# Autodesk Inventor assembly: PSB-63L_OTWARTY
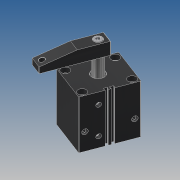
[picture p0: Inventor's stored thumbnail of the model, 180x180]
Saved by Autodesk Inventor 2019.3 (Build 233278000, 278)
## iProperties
Company: Î¢ÈíÖÐ¹ú
Created: 2013-04
Part Number: PSB-63L_OTWARTY
Material: Ogólny
Description: STEP AP203
Document SubType Name: Assembly
Designer: CADENGINEERING4
Sending System: SolidWorks 2010
Preprocessor: SwSTEP 2.0
Title: PSB-L6390-1515-00.STEP
Author: Î¢ÈíÓÃ»§
Revision Number: ÈÎºÎ
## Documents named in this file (11)
- E:\SERWER_ZAPAS\Pneumatic\PSB PNEUMATIC SWING\PSB-63\PSB-63L_OTWARTY.iam
- E:\SERWER_ZAPAS\Pneumatic\PSB PNEUMATIC SWING\PSB-63\PSB-L63-90-15-15-01.ipt
- E:\SERWER_ZAPAS\Pneumatic\PSB PNEUMATIC SWING\PSB-63\¸ÖÖé4.ipt
- E:\SERWER_ZAPAS\Pneumatic\PSB PNEUMATIC SWING\PSB-63\hex socket set screws with flat point gb_GB_FASTENER_SCREWS_HSFP M5X8-N.ipt
- E:\SERWER_ZAPAS\Pneumatic\PSB PNEUMATIC SWING\PSB-63\PSB-L63-90-15-15-04.ipt
- E:\SERWER_ZAPAS\Pneumatic\PSB PNEUMATIC SWING\PSB-63\PSB-L63-90-15-15-02.ipt
- E:\SERWER_ZAPAS\Pneumatic\PSB PNEUMATIC SWING\PSB-63\PSB-L63-90-15-15-05.ipt
- E:\SERWER_ZAPAS\Pneumatic\PSB PNEUMATIC SWING\PSB-63\hexagon socket head cap screws gb_GB_FASTENER_SCREWS_HSHCS M10X20-N.ipt
- E:\SERWER_ZAPAS\Pneumatic\PSB PNEUMATIC SWING\PSB-63\s¸Ë2.ipt
- E:\SERWER_ZAPAS\Pneumatic\PSB PNEUMATIC SWING\PSB-63\PSB-L63-90-15-15-03.ipt
- E:\SERWER_ZAPAS\Pneumatic\PSB PNEUMATIC SWING\PSB-63\4x40.ipt
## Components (14 placed, 14 different names)
1. PSB-L63-90-15-15-01_1 — Zestawiające:1, Zestawiające:2, Zestawiające:4, Kątowe:1
2. ¸ÖÖé4_2 — Zestawiające:10
3. hex socket set screws with flat point gb_GB_FASTENER_SCREWS_HSFP M5X8-N_3 — Zestawiające:10
4. hex socket set screws with flat point gb_GB_FASTENER_SCREWS_HSFP M5X8-N_4 — Zestawiające:12
5. PSB-L63-90-15-15-04_5 — Zestawiające:5, Równoległe:1, Zestawiające:6, Zestawiające:9, Zestawiające:14, Kątowe:1
6. PSB-L63-90-15-15-02_6 — Zestawiające:3, Zestawiające:4, Zestawiające:5, Zestawiające:13, Równoległe:2
7. PSB-L63-90-15-15-05_7 — Równoległe:1, Zestawiające:6, Zestawiające:8
8. ¸ÖÖé4_8 — Zestawiające:12
9. hexagon socket head cap screws gb_GB_FASTENER_SCREWS_HSHCS M10X20-N_9 — Zestawiające:1, Zestawiające:2, Zestawiające:3
10. s¸Ë2_10 — Zestawiające:7, Zestawiające:9
11. ¸ÖÖé4_11 — Zestawiające:11
12. PSB-L63-90-15-15-03_12 — Zestawiające:13, Równoległe:2, Zestawiające:14
13. 4x40_13 — Zestawiające:7, Zestawiające:8
14. hex socket set screws with flat point gb_GB_FASTENER_SCREWS_HSFP M5X8-N_14 — Zestawiające:11
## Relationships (17: Mate 14, Flush 2, Angle 1)
- Zestawiające:1 [Mate]: PSB-L63-90-15-15-01_1 ↔ hexagon socket head cap screws gb_GB_FASTENER_SCREWS_HSHCS M10X20-N_9
- Zestawiające:2 [Mate]: PSB-L63-90-15-15-01_1 ↔ hexagon socket head cap screws gb_GB_FASTENER_SCREWS_HSHCS M10X20-N_9
- Zestawiające:3 [Mate]: PSB-L63-90-15-15-02_6 ↔ hexagon socket head cap screws gb_GB_FASTENER_SCREWS_HSHCS M10X20-N_9
- Zestawiające:4 [Mate]: PSB-L63-90-15-15-01_1 ↔ PSB-L63-90-15-15-02_6
- Zestawiające:5 [Mate]: PSB-L63-90-15-15-04_5 ↔ PSB-L63-90-15-15-02_6
- Równoległe:1 [Flush]: PSB-L63-90-15-15-04_5 ↔ PSB-L63-90-15-15-05_7
- Zestawiające:6 [Mate]: PSB-L63-90-15-15-04_5 ↔ PSB-L63-90-15-15-05_7
- Zestawiające:7 [Mate]: s¸Ë2_10 ↔ 4x40_13
- Zestawiające:8 [Mate]: PSB-L63-90-15-15-05_7 ↔ 4x40_13
- Zestawiające:9 [Mate]: PSB-L63-90-15-15-04_5 ↔ s¸Ë2_10
- Zestawiające:10 [Mate]: ¸ÖÖé4_2 ↔ hex socket set screws with flat point gb_GB_FASTENER_SCREWS_HSFP M5X8-N_3
- Zestawiające:11 [Mate]: ¸ÖÖé4_11 ↔ hex socket set screws with flat point gb_GB_FASTENER_SCREWS_HSFP M5X8-N_14
- Zestawiające:12 [Mate]: hex socket set screws with flat point gb_GB_FASTENER_SCREWS_HSFP M5X8-N_4 ↔ ¸ÖÖé4_8
- Zestawiające:13 [Mate]: PSB-L63-90-15-15-02_6 ↔ PSB-L63-90-15-15-03_12
- Równoległe:2 [Flush]: PSB-L63-90-15-15-02_6 ↔ PSB-L63-90-15-15-03_12
- Zestawiające:14 [Mate]: PSB-L63-90-15-15-04_5 ↔ PSB-L63-90-15-15-03_12
- Kątowe:1 [Angle]: PSB-L63-90-15-15-01_1 ↔ PSB-L63-90-15-15-04_5
